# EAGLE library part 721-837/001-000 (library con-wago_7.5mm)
Serie 721, Stiftleiste (für Leiterplatten) Einlötstift abgewinkelt 1 x 1 mm / Series 721, Male header (for PCBs) Angled solder pin 1 x 1 mm Polzahl / Pole No.: 7 Rastermaß / Pitch: 7.5 mm Bemessungsspannung / Rated Voltage: 630 V Nennstrom / Nominal Current: 12 A Lötstiftlänge: / Solder Pin Length: 3.8 mm Farbe / Color: lichtgrau / light gray Stand: 01.01.2012. Die jeweils aktuellen Daten zu diesem Artikel finden Sie in unserem Produktkatalog, den Sie unter www.wago.com einsehen können. As of: 01/01/2012. Please find the newest data for this article in our product catalogue, which can be viewed under www.wago.com.
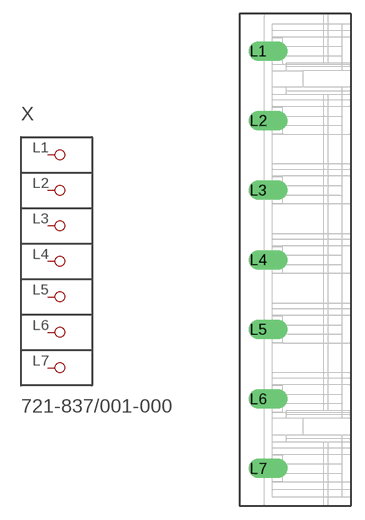
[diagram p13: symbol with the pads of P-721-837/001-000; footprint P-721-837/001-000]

Designator prefix X

## 721-837/001-000  [P-721-837/001-000]
L1  P1
L2  P2
L3  P3
L4  P4
L5  P5
L6  P6
L7  P7

## Footprint P-721-837/001-000 (pad centres in mm)
drill 1.4 offset: L1 -4,22.5; L2 -4,15; L3 -4,7.5; L4 -4,0; L5 -4,-7.5; L6 -4,-15; L7 -4,-22.5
